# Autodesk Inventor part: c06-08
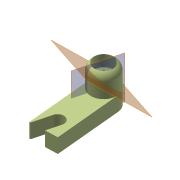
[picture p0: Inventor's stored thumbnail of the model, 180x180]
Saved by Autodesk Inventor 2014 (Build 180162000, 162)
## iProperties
Created: 2013-03
Part Number: c06-08
Material: Aluminum 6061
Document SubType Name: Modeling
Designer: Thom Tremblay
Density: 2.71 g/cm^3
Appearance: Zinc Chromate 2
Author: Thom Tremblay
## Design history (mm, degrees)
sketch "Sketch1"
  geometry: L1 (0, -12.5)-(60, -12.5); L2 (60, -12.5)-(60, 12.5); L3 (60, 12.5)-(0, 12.5); L4 (0, 12.5)-(0, -12.5); 2 further points
  constraints: 8 end point, 2 parallel, 1 coincident, 1 horizontal, 1 midpoint, 1 perpendicular
  dimensions: "d1" = 25 distance of L2.end L1.end; "d2" = 60 distance of L2.end L3.end
extrude "Base" new body sketch "Sketch1" distance "d3" = 14; taper "d4" = 0 deg
sketch "Sketch2"
  geometry: C1 r 12.5 at (0, 0); 1 further point
  constraints: 1 centre point, 1 coincident
extrude "Boss" join sketch "Sketch2" distance "d5" = 35; taper "d6" = 0 deg
sketch "Sketch3"
  geometry: L1 (-60, 12.5)-(-60, -12.5) reference; L2 (-60, -6)-(-60, 6); L3 (-43.948, 5.638)-(-60, 11.481); L4 (-48.052, -5.638)-(-60, -1.289); L5 (-60, 11.481)-(-60, -1.289); A1 r 6 centre (-46, 0) between (-43.948, 5.638) and (-48.052, -5.638); 2 further points
  constraints: 8 end point, 3 midpoint, 2 point on circle, 2 point on line, 2 tangent, 1 centre point, 1 collinear, 1 horizontal alignment, 1 parallel
  dimensions: "d8" = 12 diameter of A1; "d20" = 20 dimension on A1 L1; "d27" = 70 deg angle of L1 L3
extrude "Slot" cut sketch "Sketch3" stored distance "d9" = 24; taper "d10" = 0 deg
hole "Hole1" diameter "d13" = 11; stored, may be unused: countersink angle "d17" = 90 deg, drill point angle "d19" = 118 deg; dims "d11" = 10, "d12" = 10, "d14" = 6, "d15" = 18, "d16" = 11, "d18" = 8
fillet "Fillet1" dims "d26" = 8
node "Midplane between faces"
node "Normal to Edge at Point"
node "Offset Plane"
  node "Tangent Plane"
sketch "Sketch4"
  geometry: L1 (0, 0)-(-60, 0) reference; L2 (-14, 0)-(-18.341, 24.62)
  constraints: 2 end point, 1 point on line
  dimensions: "d21" = 25 distance of L2.start L2.end; "d22" = 80 deg angle of L1 L2; "d23" = 14 distance of L1.start L2.start
node "Plane at Angle on Sketch"
sketch "Sketch5"
  geometry: L1 (0, 0)-(-19.151, 16.07); L2 (0, 0)-(25, 0); C1 r 9 at (0, 0) reference; C2 r 5.5 at (0, 0) reference
  constraints: 4 end point, 1 equal length, 1 horizontal
  dimensions: "d24" = 25 distance of L1.start L1.end; "d25" = 140 deg angle of L2 L1
node "Plane using Sketch as Axis"
workplane "Work Plane8"
workplane "Work Plane10"
  workaxis "Work Axis2"
workplane "Work Plane11"
body "Solid1"
workaxis "Work Axis1"
node "Plane at Angle"
workplane "Work Plane9"
other parameters: "d28" = 30 deg, "d29" = 15, "d30" = 90 deg, "d37" = 90 deg, "d38" = 8, "d39" = 45 deg, "d40" = 90 deg
